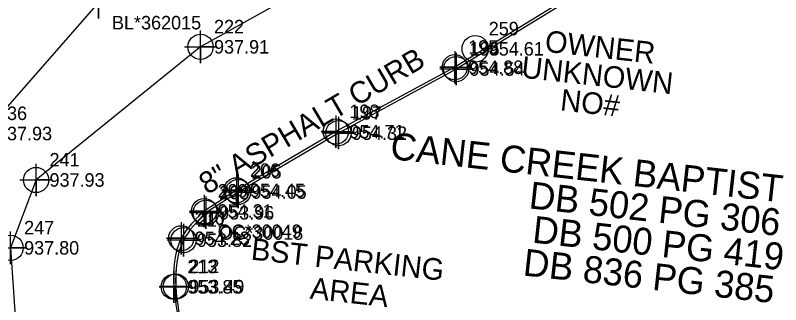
# Model space of a CAD drawing. Extents: x 1150279 to 1151282, y 654632 to 657999.
# Drawn here: x 1150767.1 to 1150909.2, y 657165.5 to 657219.1 of the extents above; entities that cross this region are included whole.
import ezdxf

# ---------------------------------------------------------------- set-up
doc = ezdxf.new("R2010")
doc.units = 0
for name, color, linetype in [('Exist Hydro Jurisdictional Stream or Body of Water', 7, 'Continuous'), ('Exist Hydro Stream or Body of Water Cogo Comment', 7, 'Continuous'), ('Exist Hydro Stream or Body of Water Cogo Elevation', 7, 'Continuous'), ('Exist Hydro Stream or Body of Water Cogo Number', 7, 'Continuous'), ('Exist Hydro Stream or Body of Water Cogo Point CELL', 7, 'Continuous'), ('Exist Property Deed Book Text', 7, 'Continuous'), ('Exist Property Owner Text', 7, 'Continuous'), ('Exist Roads Curbs', 7, 'Continuous'), ('Exist Roads Curbs Cogo Comment', 7, 'Continuous'), ('Exist Roads Curbs Cogo Elevation', 7, 'Continuous'), ('Exist Roads Curbs Cogo Number', 7, 'Continuous'), ('Exist Roads Curbs Cogo Point CELL', 7, 'Continuous'), ('Exist Roads Curbs Text', 7, 'Continuous'), ('Exist Roads EOP', 7, 'Continuous'), ('Exist Roads EOP Cogo Comment', 7, 'Continuous'), ('Exist Roads EOP Cogo Elevation', 7, 'Continuous'), ('Exist Roads EOP Cogo Number', 7, 'Continuous'), ('Exist Roads EOP Cogo Point CELL', 7, 'Continuous'), ('Exist Roads EOP Text', 7, 'Continuous'), ('Exist Utilities Other Pole CELL', 7, 'Continuous'), ('Exist Utilities Other Pole Cogo Elevation', 7, 'Continuous'), ('Exist Utilities Other Pole Cogo Number', 7, 'Continuous'), ('Exist Utilities Other Pole Text', 7, 'Continuous')]:
    doc.layers.add(name, color=color, linetype=linetype)

msp = doc.modelspace()

# ---------------------------------------------------------------- linework, layer by layer
at = {"layer": 'Exist Hydro Jurisdictional Stream or Body of Water'}
for points in [[(1150876.79, 657253.09), (1150843.42, 657236.68), (1150801.48, 657213.29), (1150770.94, 657188.61), (1150766.22, 657176.03), (1150768.22, 657146.09), (1150768.31, 657144.46)], [(1150782.54, 657221.52), (1150761.19, 657197.22), (1150753.72, 657183.88), (1150744.98, 657145.96), (1150745.06, 657143.83)]]:
    msp.add_lwpolyline(points, dxfattribs=at)
at = {"layer": 'Exist Hydro Stream or Body of Water Cogo Point CELL'}
for points in [[(1150779.54, 657221.52), (1150785.54, 657221.52), (1150782.54, 657221.52), (1150782.54, 657218.52), (1150782.54, 657224.52)], [(1150798.48, 657213.29), (1150804.48, 657213.29), (1150801.48, 657213.29), (1150801.48, 657210.29), (1150801.48, 657216.29)], [(1150767.94, 657188.61), (1150773.94, 657188.61), (1150770.94, 657188.61), (1150770.94, 657185.61), (1150770.94, 657191.61)], [(1150763.22, 657176.03), (1150769.22, 657176.03), (1150766.22, 657176.03), (1150766.22, 657173.03), (1150766.22, 657179.03)]]:
    msp.add_lwpolyline(points, dxfattribs=at)
for centre in [(1150801.48, 657213.29), (1150770.94, 657188.61), (1150766.22, 657176.03)]:
    msp.add_circle(centre, 2.34, dxfattribs=at)
at = {"layer": 'Exist Roads Curbs'}
msp.add_lwpolyline([(1150881.81, 657229.85), (1150848.66, 657209.5), (1150826.61, 657197.58), (1150808.15, 657186.69), (1150802.15, 657182.85)], dxfattribs=at)
msp.add_spline([(1150802.15, 657182.85), (1150797.9, 657177.8), (1150796.53, 657168.81), (1150797.9, 657160.14)], degree=3, dxfattribs=at)
at = {"layer": 'Exist Roads Curbs Cogo Point CELL'}
for points in [[(1150848.66, 657212.5), (1150848.66, 657206.5), (1150848.66, 657209.5), (1150845.93, 657209.5), (1150851.66, 657209.5)], [(1150826.61, 657200.58), (1150826.61, 657194.58), (1150826.61, 657197.58), (1150823.88, 657197.58), (1150829.61, 657197.58)], [(1150808.15, 657189.69), (1150808.15, 657183.69), (1150808.15, 657186.69), (1150805.42, 657186.69), (1150811.15, 657186.69)], [(1150802.15, 657185.85), (1150802.15, 657179.85), (1150802.15, 657182.85), (1150799.42, 657182.85), (1150805.15, 657182.85)], [(1150797.9, 657180.8), (1150797.9, 657174.8), (1150797.9, 657177.8), (1150795.17, 657177.8), (1150800.9, 657177.8)], [(1150796.53, 657171.81), (1150796.53, 657165.81), (1150796.53, 657168.81), (1150793.8, 657168.81), (1150799.53, 657168.81)]]:
    msp.add_lwpolyline(points, dxfattribs=at)
for centre in [(1150848.66, 657209.5), (1150826.61, 657197.58), (1150808.15, 657186.69), (1150802.15, 657182.85), (1150797.9, 657177.8), (1150796.53, 657168.81)]:
    msp.add_circle(centre, 2.34, dxfattribs=at)
at = {"layer": 'Exist Roads EOP'}
msp.add_lwpolyline([(1150882.15, 657229.46), (1150848.92, 657209.17), (1150827.08, 657197.29), (1150808.45, 657186.38), (1150802.44, 657182.53)], dxfattribs=at)
msp.add_spline([(1150802.44, 657182.53), (1150798.31, 657177.45), (1150796.89, 657168.84), (1150798.26, 657160.11)], degree=3, dxfattribs=at)
at = {"layer": 'Exist Roads EOP Cogo Point CELL'}
for points in [[(1150848.92, 657212.17), (1150848.92, 657206.17), (1150848.92, 657209.17), (1150851.92, 657209.17), (1150845.92, 657209.17)], [(1150827.08, 657200.29), (1150827.08, 657194.29), (1150827.08, 657197.29), (1150830.08, 657197.29), (1150824.08, 657197.29)], [(1150808.45, 657189.38), (1150808.45, 657183.38), (1150808.45, 657186.38), (1150811.45, 657186.38), (1150805.45, 657186.38)], [(1150802.44, 657185.53), (1150802.44, 657179.53), (1150802.44, 657182.53), (1150805.44, 657182.53), (1150799.44, 657182.53)], [(1150798.31, 657180.45), (1150798.31, 657174.45), (1150798.31, 657177.45), (1150801.31, 657177.45), (1150795.31, 657177.45)], [(1150796.89, 657171.84), (1150796.89, 657165.84), (1150796.89, 657168.84), (1150799.89, 657168.84), (1150793.89, 657168.84)]]:
    msp.add_lwpolyline(points, dxfattribs=at)
for centre in [(1150848.92, 657209.17), (1150827.08, 657197.29), (1150808.45, 657186.38), (1150802.44, 657182.53), (1150798.31, 657177.45), (1150796.89, 657168.84)]:
    msp.add_circle(centre, 2.34, dxfattribs=at)
at = {"layer": 'Exist Utilities Other Pole CELL'}
msp.add_circle((1150852.48, 657212.92), 2.46, dxfattribs=at)

# ---------------------------------------------------------------- texts
at = {"layer": 'Exist Hydro Stream or Body of Water Cogo Comment'}
msp.add_text('BL*362015', height=2.5, dxfattribs=at).set_placement((1150785.04, 657216.52))
at = {"layer": 'Exist Hydro Stream or Body of Water Cogo Elevation'}
for s, p in [('937.91', (1150803.98, 657212.04)), ('937.93', (1150763.69, 657195.97)), ('937.93', (1150773.44, 657187.36)), ('937.80', (1150768.72, 657174.78))]:
    msp.add_text(s, height=2.5, dxfattribs=at).set_placement(p)
at = {"layer": 'Exist Hydro Stream or Body of Water Cogo Number'}
for s, p in [('222', (1150803.98, 657215.79)), ('236', (1150763.69, 657199.72)), ('241', (1150773.44, 657191.11)), ('247', (1150768.72, 657178.53))]:
    msp.add_text(s, height=2.5, dxfattribs=at).set_placement(p)
at = {"layer": 'Exist Property Deed Book Text'}
for s, p in [('DB 502 PG 306', (1150862.3, 657183.37)), ('DB 500 PG 419', (1150862.94, 657177.01)), ('DB 836 PG 385', (1150861.2, 657170.92))]:
    msp.add_text(s, height=5, rotation=353.6867, dxfattribs=at).set_placement(p)
at = {"layer": 'Exist Property Owner Text'}
msp.add_text('CANE CREEK BAPTIST CHURCH', height=5, rotation=353.6867, dxfattribs=at).set_placement((1150836.54, 657192.51))
at = {"layer": 'Exist Roads Curbs Cogo Comment'}
msp.add_text('OC*30049', height=2.5, dxfattribs=at).set_placement((1150804.65, 657177.85))
at = {"layer": 'Exist Roads Curbs Cogo Elevation'}
for s, p in [('954.88', (1150851.16, 657208.25)), ('954.71', (1150829.11, 657196.33)), ('954.45', (1150810.65, 657185.44)), ('954.31', (1150804.65, 657181.6)), ('954.23', (1150800.4, 657176.55)), ('953.85', (1150799.03, 657167.56))]:
    msp.add_text(s, height=2.5, dxfattribs=at).set_placement(p)
at = {"layer": 'Exist Roads Curbs Cogo Number'}
for s, p in [('195', (1150851.16, 657212)), ('198', (1150829.11, 657200.08)), ('206', (1150810.65, 657189.19)), ('209', (1150804.65, 657185.35)), ('210', (1150800.4, 657180.3)), ('213', (1150799.03, 657171.31))]:
    msp.add_text(s, height=2.5, dxfattribs=at).set_placement(p)
at = {"layer": 'Exist Roads Curbs Text'}
msp.add_text('8" ASPHALT CURB', height=4, rotation=30.5305, dxfattribs=at).set_placement((1150802.71, 657185.81))
at = {"layer": 'Exist Roads EOP Cogo Comment'}
msp.add_text('OC*30018', height=2.5, dxfattribs=at).set_placement((1150804.94, 657177.53))
at = {"layer": 'Exist Roads EOP Cogo Elevation'}
for s, p in [('954.54', (1150851.42, 657207.92)), ('954.32', (1150829.58, 657196.04)), ('954.05', (1150810.95, 657185.13)), ('953.96', (1150804.94, 657181.28)), ('953.82', (1150800.81, 657176.2)), ('953.49', (1150799.39, 657167.59))]:
    msp.add_text(s, height=2.5, dxfattribs=at).set_placement(p)
at = {"layer": 'Exist Roads EOP Cogo Number'}
for s, p in [('196', (1150851.42, 657211.67)), ('197', (1150829.58, 657199.79)), ('205', (1150810.95, 657188.88)), ('208', (1150804.94, 657185.03)), ('211', (1150800.81, 657179.95)), ('212', (1150799.39, 657171.34))]:
    msp.add_text(s, height=2.5, dxfattribs=at).set_placement(p)
at = {"layer": 'Exist Roads EOP Text'}
for s, p in [('BST PARKING', (1150810.72, 657173.87)), ('AREA', (1150821.67, 657166.62))]:
    msp.add_text(s, height=4, rotation=353.6867, dxfattribs=at).set_placement(p)
at = {"layer": 'Exist Utilities Other Pole Cogo Elevation'}
msp.add_text('954.61', height=2.5, dxfattribs=at).set_placement((1150854.98, 657211.67))
at = {"layer": 'Exist Utilities Other Pole Cogo Number'}
msp.add_text('259', height=2.5, dxfattribs=at).set_placement((1150854.98, 657215.42))
at = {"layer": 'Exist Utilities Other Pole Text'}
for s, p in [('OWNER', (1150865.27, 657212.4)), ('UNKNOWN', (1150860.91, 657207.6)), ('NO#', (1150868.13, 657201.52))]:
    msp.add_text(s, height=4, rotation=353.6867, dxfattribs=at).set_placement(p)

doc.saveas('drawing.dxf')
